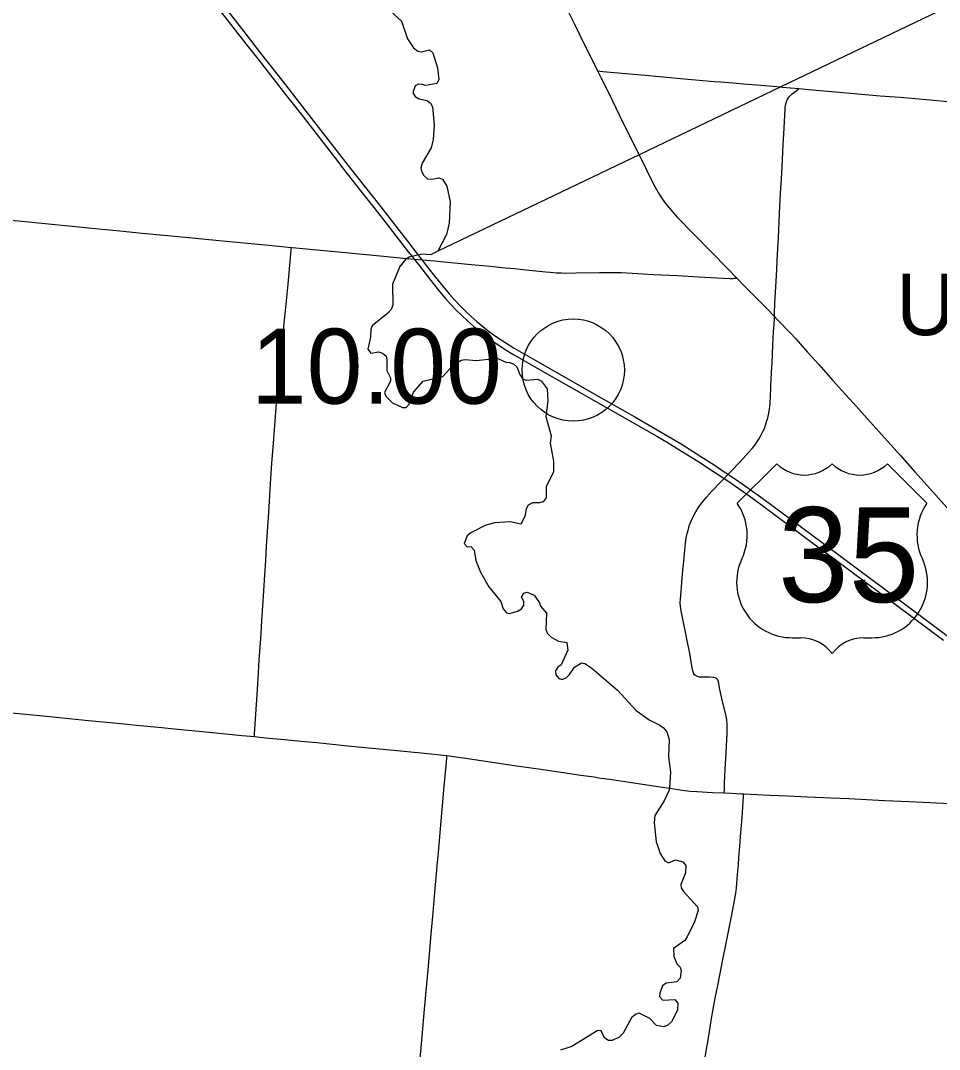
# Model space of a CAD drawing. Extents: x 1597222 to 1925846, y 496284 to 911751.
# Drawn here: x 1674019 to 1687501, y 561679 to 576766 of the extents above; entities that cross this region are included whole.
import ezdxf

# ---------------------------------------------------------------- set-up
doc = ezdxf.new("R2010")
doc.units = 0
for name, color, linetype in [('Default', 7, 'Continuous'), ('GM_X_County_Road', 7, 'Continuous'), ('GM_X_Township', 7, 'Continuous'), ('GM_X_Township_Road', 7, 'Continuous'), ('GM_X_Township_Text', 7, 'Continuous'), ('GM_X_US_Route', 7, 'Continuous'), ('GM_X_US_Shield', 7, 'Continuous')]:
    doc.layers.add(name, color=color, linetype=linetype)

msp = doc.modelspace()

# ---------------------------------------------------------------- linework, layer by layer
at = {"layer": 'Default'}
msp.add_circle((1682128, 571641), 750, dxfattribs=at)
msp.add_circle((1682128, 571641), 750, dxfattribs=at)
at = {"layer": 'GM_X_County_Road'}
for points in [[(1681413, 578092), (1681415, 578089), (1681463, 578023), (1681518, 577941), (1681569, 577858), (1681618, 577772), (1681672, 577671), (1681737, 577539), (1681817, 577377), (1682021, 576966), (1682145, 576715), (1682225, 576554), (1682484, 576030)], [(1682484, 576030), (1682538, 575920), (1682633, 575730), (1682872, 575244), (1683094, 574796)], [(1682484, 576030), (1682561, 576020), (1682953, 575985), (1683182, 575964), (1683394, 575946), (1683753, 575912), (1684194, 575873), (1684293, 575866), (1684472, 575854), (1684619, 575841), (1684881, 575818), (1685060, 575803), (1685176, 575793)], [(1685176, 575793), (1685191, 575792), (1685437, 575768)], [(1685437, 575768), (1685632, 575750), (1685975, 575719), (1686302, 575692), (1686629, 575665), (1686923, 575641), (1687364, 575602), (1687675, 575577), (1687903, 575557), (1688116, 575540), (1688361, 575519), (1688704, 575492), (1688851, 575479), (1688998, 575466), (1689178, 575450), (1689423, 575431), (1689521, 575425), (1689630, 575418)], [(1683094, 574796), (1683207, 574568), (1683302, 574378), (1683349, 574291), (1683390, 574220), (1683435, 574151), (1683482, 574084), (1683533, 574020), (1683587, 573957), (1683654, 573885), (1684146, 573380), (1684399, 573123), (1684527, 572990)], [(1672108, 574013), (1672440, 573978), (1673550, 573870), (1674039, 573823), (1674431, 573786), (1674823, 573747), (1675067, 573723), (1675475, 573683), (1675801, 573651), (1676438, 573590), (1676732, 573562), (1677140, 573522), (1677613, 573477), (1677994, 573440)], [(1677994, 573440), (1678005, 573439), (1678364, 573405), (1678788, 573364), (1679343, 573312), (1679636, 573283), (1679690, 573278)], [(1679690, 573278), (1679792, 573269), (1679906, 573259), (1679979, 573253), (1680094, 573242), (1680229, 573229), (1680387, 573213), (1680582, 573194), (1680909, 573163), (1681130, 573142), (1681268, 573130), (1681432, 573112), (1681724, 573082), (1681791, 573075), (1681884, 573069), (1681956, 573065), (1682018, 573064), (1682165, 573065), (1682513, 573071), (1682676, 573070), (1682831, 573070), (1682990, 573063), (1683148, 573051), (1683312, 573045), (1683656, 573028), (1683967, 573010), (1684147, 573001), (1684425, 572986), (1684458, 572985), (1684474, 572985), (1684490, 572987), (1684527, 572990)], [(1684527, 572990), (1684649, 572864), (1684972, 572537), (1685081, 572425)], [(1685081, 572425), (1685120, 572384), (1685314, 572184), (1685392, 572100), (1685567, 571905), (1685731, 571722), (1685939, 571489), (1686070, 571343), (1686234, 571159), (1686694, 570647), (1686923, 570391), (1687142, 570147), (1687362, 569903), (1687656, 569573), (1687985, 569207), (1688182, 568988), (1688336, 568817), (1688543, 568584), (1688739, 568364), (1688914, 568169), (1689080, 567987), (1689171, 567892), (1689206, 567856)], [(1671504, 566869), (1671526, 566862), (1671573, 566851), (1671638, 566840), (1671735, 566827), (1671980, 566801), (1672208, 566778), (1672388, 566760), (1672731, 566727), (1673008, 566700), (1673286, 566673), (1673939, 566610), (1674200, 566584), (1674543, 566549), (1675017, 566504), (1675278, 566478), (1675539, 566452), (1675719, 566435), (1676094, 566398), (1676323, 566377), (1676633, 566345), (1677270, 566283), (1677449, 566266)], [(1677449, 566266), (1677613, 566250), (1677890, 566223), (1678135, 566199), (1678364, 566178), (1678821, 566131), (1679278, 566085), (1679490, 566065), (1679899, 566026), (1680274, 565988)], [(1679853, 561217), (1679916, 561920), (1679941, 562215), (1679983, 562689), (1680002, 562901), (1680047, 563424), (1680071, 563686), (1680096, 563980), (1680110, 564144), (1680131, 564372), (1680150, 564568), (1680178, 564912), (1680198, 565141), (1680213, 565304), (1680228, 565484), (1680266, 565892), (1680272, 565958), (1680274, 565988)], [(1680274, 565988), (1680404, 565971), (1680583, 565945), (1680778, 565915), (1680972, 565886), (1681264, 565843), (1681719, 565778), (1681979, 565741), (1682239, 565703), (1682433, 565674), (1682531, 565659), (1682661, 565641), (1682823, 565618), (1682985, 565593), (1683342, 565538), (1683537, 565510), (1683538, 565509)], [(1683538, 565509), (1683666, 565490), (1683764, 565476), (1683845, 565467), (1683943, 565460), (1684172, 565447), (1684343, 565440)], [(1684343, 565440), (1684451, 565435), (1684598, 565428), (1684630, 565427)], [(1684630, 565427), (1684729, 565423), (1685008, 565409), (1685270, 565397), (1685565, 565383), (1685909, 565366), (1686171, 565356), (1686696, 565330), (1687056, 565313), (1687761, 565278), (1687950, 565269)]]:
    msp.add_lwpolyline(points, dxfattribs=at)
at = {"layer": 'GM_X_Township'}
for points in [[(1691219, 578692), (1690506, 578351), (1685176, 575796), (1683094, 574797), (1680143, 573383)], [(1679443, 576909), (1679608, 576756), (1679698, 576498), (1679785, 576367), (1679849, 576319), (1679903, 576307), (1680020, 576335), (1680070, 576291), (1680138, 576072), (1680156, 575898), (1680128, 575844), (1679967, 575812), (1679913, 575830), (1679859, 575836), (1679808, 575810), (1679776, 575706), (1679808, 575651), (1679867, 575617), (1679983, 575593), (1680035, 575555), (1680063, 575499), (1680087, 575232), (1680073, 575022), (1680041, 574899), (1679912, 574677), (1679894, 574609), (1679900, 574556), (1679935, 574496), (1679989, 574444), (1680047, 574440), (1680159, 574460), (1680212, 574442), (1680272, 574338), (1680322, 574107), (1680306, 573796), (1680268, 573628), (1680143, 573383), (1680091, 573358), (1680035, 573331), (1679906, 573341), (1679721, 573299), (1679695, 573283), (1679671, 573269), (1679584, 573161), (1679478, 572900), (1679480, 572591), (1679458, 572531), (1679409, 572475), (1679176, 572289), (1679156, 572239), (1679154, 572124), (1679116, 571948), (1679160, 571888), (1679271, 571910), (1679327, 571889), (1679383, 571843), (1679393, 571791), (1679391, 571635), (1679447, 571526), (1679447, 571476), (1679359, 571314), (1679377, 571260), (1679475, 571159), (1679622, 571091), (1679678, 571091), (1679720, 571143), (1679783, 571316), (1679925, 571476), (1680215, 571546), (1680365, 571712), (1680484, 571784), (1680540, 571794), (1680703, 571780), (1680972, 571810), (1681030, 571804), (1681141, 571758), (1681195, 571752), (1681251, 571734), (1681302, 571690), (1681344, 571575), (1681390, 571509), (1681440, 571491), (1681603, 571509), (1681659, 571481), (1681745, 571365), (1681753, 571190), (1681727, 570961), (1681803, 570677), (1681787, 570568), (1681839, 570305), (1681837, 570145), (1681733, 569934), (1681733, 569766), (1681689, 569710), (1681634, 569692), (1681530, 569692), (1681468, 569658), (1681437, 569604), (1681417, 569493), (1681361, 569383), (1681202, 569415), (1680975, 569401), (1680845, 569369), (1680626, 569255), (1680573, 569209), (1680529, 569099), (1680573, 569047), (1680626, 569053), (1680676, 569000), (1680700, 568848), (1680766, 568679), (1680887, 568461), (1681067, 568246), (1681099, 568138), (1681148, 568082), (1681198, 568071), (1681310, 568106), (1681369, 568138), (1681401, 568192), (1681403, 568246), (1681371, 568312), (1681403, 568370), (1681453, 568386), (1681553, 568342), (1681632, 568230), (1681648, 568180), (1681736, 568075), (1681724, 567837), (1681750, 567776), (1681802, 567726), (1681913, 567668), (1682035, 567646), (1682049, 567533), (1681951, 567321), (1681901, 567283), (1681868, 567231), (1681874, 567173), (1681915, 567118), (1681965, 567102), (1682023, 567128), (1682075, 567176), (1682144, 567283), (1682248, 567349), (1682298, 567337), (1682403, 567271), (1682776, 566945), (1683051, 566648), (1683240, 566510), (1683397, 566434), (1683453, 566397), (1683501, 566337), (1683537, 566223), (1683527, 565970), (1683555, 565744), (1683538, 565516), (1683535, 565481), (1683463, 565325), (1683326, 565108), (1683314, 565004), (1683346, 564725), (1683362, 564669), (1683402, 564553), (1683472, 564442), (1683525, 564414), (1683629, 564460), (1683734, 564430), (1683782, 564376), (1683776, 564268), (1683707, 564099), (1683713, 564049), (1683745, 563995), (1683952, 563772), (1683960, 563718), (1683906, 563548), (1683799, 563331), (1683763, 563275), (1683600, 563159), (1683602, 563043), (1683647, 562934), (1683699, 562884), (1683713, 562834), (1683695, 562722), (1683646, 562670), (1683492, 562648), (1683439, 562612), (1683397, 562503), (1683395, 562453), (1683443, 562399), (1683620, 562411), (1683662, 562357), (1683658, 562253), (1683570, 562082), (1683514, 562036), (1683457, 562012), (1683349, 562028), (1683250, 562131), (1683096, 562209), (1683042, 562189), (1682981, 562141), (1682861, 561916), (1682796, 561854), (1682694, 561808), (1682644, 561810), (1682593, 561844), (1682531, 561957), (1682481, 561953), (1682105, 561724), (1681940, 561668)]]:
    msp.add_lwpolyline(points, dxfattribs=at)
at = {"layer": 'GM_X_Township_Road'}
for points in [[(1685081, 572425), (1685081, 572466), (1685088, 572627), (1685099, 572856), (1685113, 573118), (1685121, 573249), (1685130, 573430), (1685137, 573577), (1685156, 573938), (1685171, 574233), (1685181, 574446), (1685191, 574626), (1685202, 574839), (1685208, 574953), (1685216, 575101), (1685231, 575379), (1685235, 575461), (1685239, 575494), (1685244, 575526), (1685252, 575558), (1685262, 575589), (1685268, 575605), (1685276, 575619), (1685285, 575633), (1685295, 575646), (1685306, 575658), (1685317, 575670), (1685342, 575691), (1685369, 575710), (1685401, 575734), (1685437, 575768)], [(1677449, 566266), (1677452, 566309), (1677488, 566882), (1677504, 567112), (1677522, 567390), (1677542, 567701), (1677559, 567963), (1677586, 568405), (1677601, 568635), (1677616, 568847), (1677629, 569060), (1677656, 569486), (1677671, 569715), (1677688, 569977), (1677707, 570272), (1677729, 570567), (1677758, 570959), (1677773, 571156), (1677784, 571270), (1677803, 571449), (1677819, 571613), (1677846, 571907), (1677862, 572070), (1677883, 572282), (1677910, 572560), (1677943, 572903), (1677958, 573066), (1677984, 573344), (1677991, 573409), (1677994, 573440)], [(1685029, 571418), (1685032, 571497), (1685038, 571612), (1685045, 571743), (1685052, 571874), (1685057, 572005), (1685062, 572103), (1685068, 572201), (1685076, 572316), (1685080, 572398), (1685081, 572425)], [(1683750, 568838), (1683765, 569001), (1683775, 569099), (1683787, 569180), (1683800, 569244), (1683817, 569308), (1683831, 569355), (1683854, 569416), (1683873, 569461), (1683902, 569520), (1683926, 569564), (1683960, 569619), (1683998, 569673), (1684038, 569725), (1684081, 569775), (1684158, 569860), (1684294, 570002), (1684341, 570051), (1684401, 570113), (1684464, 570180), (1684623, 570346), (1684701, 570430), (1684755, 570492), (1684795, 570544), (1684823, 570584), (1684849, 570626), (1684882, 570683), (1684911, 570742), (1684932, 570786), (1684949, 570833), (1684969, 570895), (1684982, 570943), (1684996, 571007), (1685006, 571072), (1685015, 571153), (1685022, 571268), (1685027, 571366), (1685029, 571418)], [(1684343, 565440), (1684345, 565491), (1684348, 565590), (1684358, 565786), (1684371, 566032), (1684384, 566311), (1684387, 566409), (1684385, 566458), (1684381, 566507), (1684375, 566540), (1684365, 566588), (1684319, 566779), (1684280, 566955), (1684257, 567068), (1684253, 567084), (1684247, 567099), (1684237, 567112), (1684225, 567122), (1684210, 567129), (1684194, 567133), (1684178, 567135), (1684128, 567136), (1684013, 567138), (1683981, 567139), (1683964, 567142), (1683949, 567146), (1683934, 567153), (1683920, 567162), (1683909, 567173), (1683899, 567187), (1683893, 567201), (1683887, 567217), (1683883, 567233), (1683874, 567281), (1683832, 567507), (1683794, 567701), (1683765, 567845), (1683737, 567990), (1683708, 568135), (1683700, 568184), (1683698, 568216), (1683698, 568233), (1683700, 568282), (1683710, 568396), (1683728, 568592), (1683742, 568756), (1683750, 568838)], [(1684041, 561422), (1684122, 561907), (1684149, 562069), (1684173, 562215), (1684201, 562376), (1684216, 562457), (1684247, 562618), (1684327, 563020), (1684365, 563213), (1684395, 563357), (1684450, 563630), (1684501, 563888), (1684515, 563969), (1684524, 564050), (1684540, 564246), (1684551, 564393), (1684559, 564491), (1684572, 564654), (1684583, 564802), (1684595, 564965), (1684604, 565079), (1684628, 565390), (1684630, 565427)]]:
    msp.add_lwpolyline(points, dxfattribs=at)
at = {"layer": 'GM_X_US_Route'}
for points in [[(1676628, 577319), (1677325, 576427), (1677518, 576182), (1677921, 575664), (1678134, 575393), (1678335, 575134), (1678638, 574746), (1678779, 574565), (1678920, 574383), (1679295, 573906), (1679526, 573608), (1679708, 573376), (1679763, 573307), (1679792, 573269), (1679871, 573169), (1680072, 572910), (1680164, 572795), (1680249, 572695), (1680325, 572609), (1680404, 572526), (1680486, 572446), (1680582, 572356), (1680668, 572280), (1680756, 572207), (1680847, 572137), (1680939, 572069), (1681034, 572004), (1681130, 571942), (1681242, 571874), (1681669, 571630), (1682639, 571078), (1682924, 570916), (1683352, 570673), (1683522, 570573), (1683718, 570453), (1683954, 570304), (1684188, 570152), (1684312, 570071), (1684341, 570051), (1684380, 570026), (1684556, 569905), (1684756, 569762), (1685060, 569538), (1685626, 569117), (1685969, 568863), (1687101, 568021), (1687562, 567679)], [(1676981, 577006), (1677293, 576604), (1677536, 576295), (1677870, 575868), (1678122, 575545), (1678324, 575287), (1678788, 574692), (1678929, 574511), (1679081, 574317), (1679303, 574033), (1679525, 573749), (1679697, 573529), (1679853, 573327), (1679906, 573259), (1680080, 573037), (1680214, 572871), (1680309, 572758), (1680385, 572672), (1680464, 572588), (1680545, 572507), (1680629, 572428), (1680715, 572352), (1680803, 572279), (1680881, 572218), (1680973, 572149), (1681054, 572093), (1681137, 572040), (1681263, 571963), (1681533, 571807), (1681989, 571547), (1682459, 571278), (1683030, 570954), (1683301, 570800), (1683527, 570668), (1683709, 570557), (1684001, 570374), (1684194, 570250), (1684344, 570151), (1684401, 570113), (1684413, 570105), (1684521, 570031), (1684722, 569890), (1684908, 569756), (1685778, 569111), (1686106, 568866), (1686699, 568426), (1686949, 568240), (1687818, 567594)]]:
    msp.add_lwpolyline(points, dxfattribs=at)
at = {"layer": 'GM_X_US_Shield'}
for p, q in [((1685114, 570268), (1684534, 569688)), ((1687318, 569688), (1686738, 570268)), ((1685346, 567716), (1685462, 567716)), ((1686390, 567716), (1686506, 567716))]:
    msp.add_line(p, q, dxfattribs=at)
for centre, radius, start, end in [((1685520, 570682), 580, 225.573, 314.427), ((1686332, 570682), 580, 225.573, 314.427), ((1683869, 569222), 812, 334.5471, 35.0009), ((1687983, 569222), 812, 144.9991, 205.4529), ((1685337, 568528), 812, 154.8319, 270.6383), ((1686515, 568528), 812, 269.3617, 25.1681), ((1685462, 567135), 580, 36.8699, 90), ((1686390, 567135), 580, 90, 143.1301)]:
    msp.add_arc(centre, radius, start, end, dxfattribs=at)

# ---------------------------------------------------------------- texts
at = {"layer": 'Default'}
msp.add_text('10.00', height=1100, dxfattribs=at).set_placement((1677399, 571148))
msp.add_text('10.00', height=1100, dxfattribs=at).set_placement((1677399, 571148))
at = {"layer": 'GM_X_Township_Text'}
msp.add_text('UNION', height=900, rotation=0, dxfattribs=at).set_placement((1686866, 572153))
at = {"layer": 'GM_X_US_Shield'}
msp.add_text('35', height=1392.2, dxfattribs=at).set_placement((1685134, 568238))

doc.saveas('drawing.dxf')
